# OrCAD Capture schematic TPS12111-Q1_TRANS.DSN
size B; title: TPS12111-Q1: 100-V Smart High Side Driver with Protection; rev: 1.0; note: Datasheet: SLUSEQ9A; note: and Diagnostics
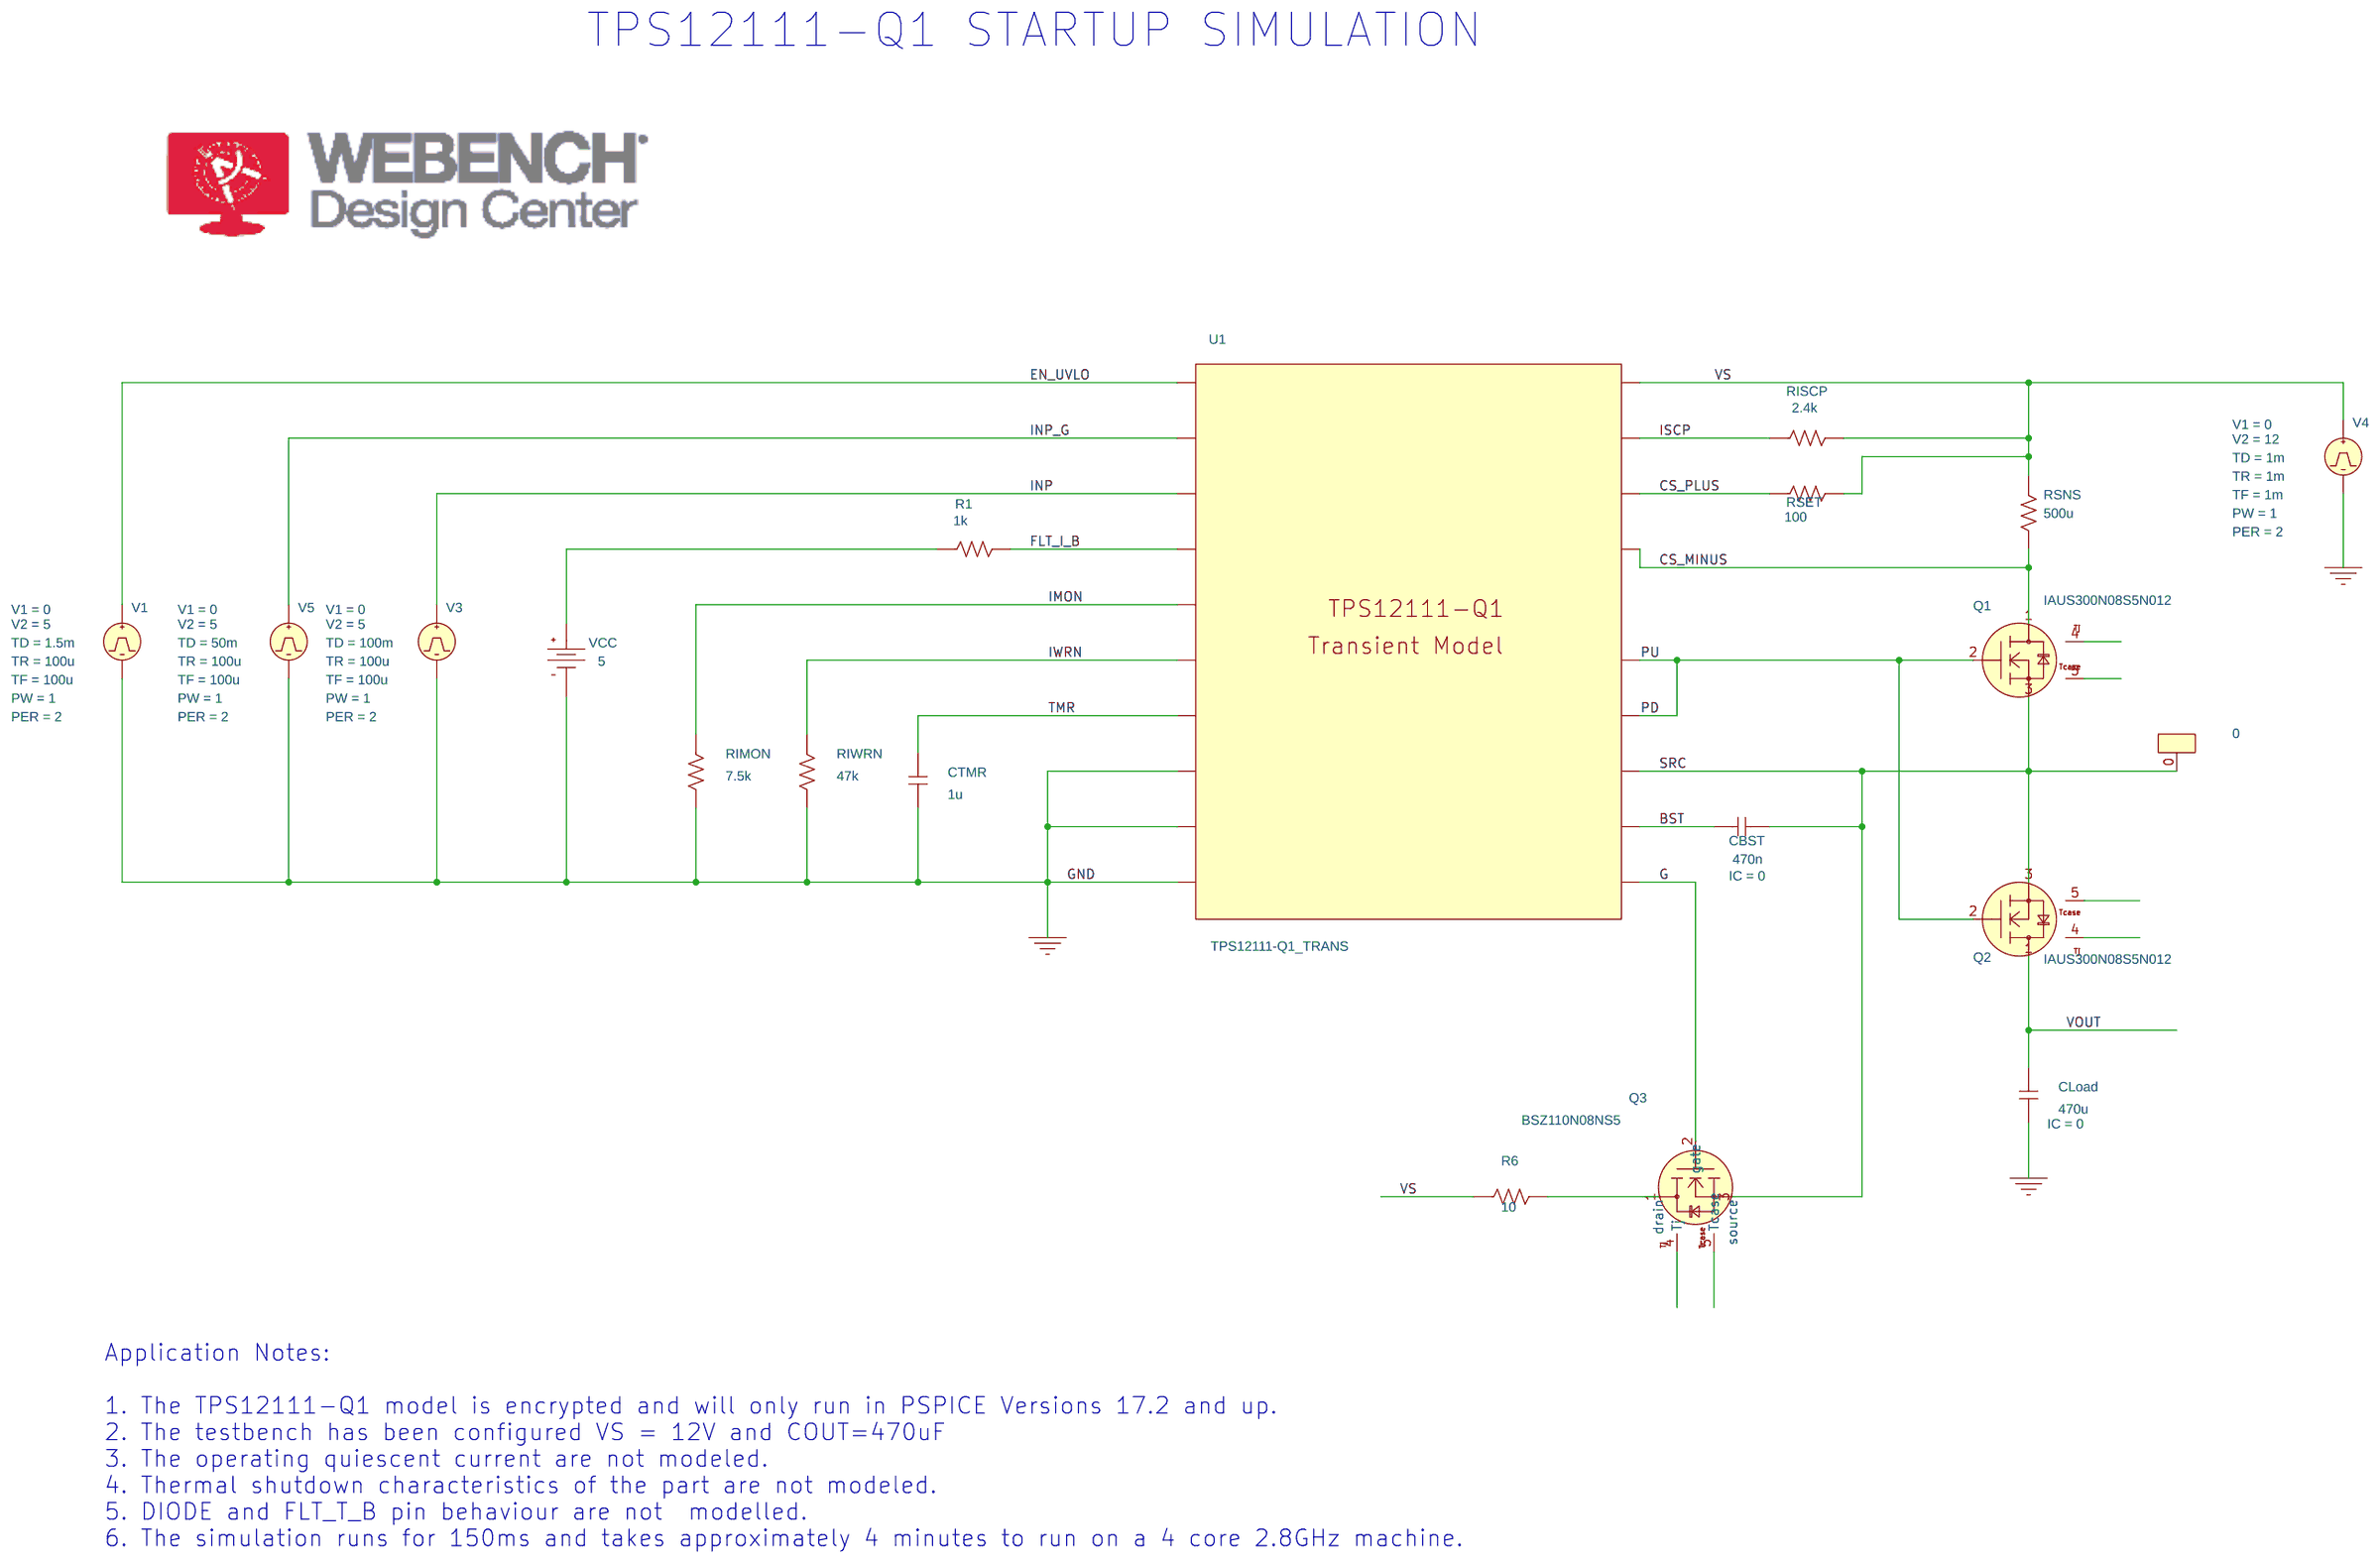
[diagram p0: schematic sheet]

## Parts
CBST  470n  [RAD/CK05]
CLoad  470u  [RAD/CK05]
CTMR  1u  [RAD/CK05]
IC1  0
Q1  IAUS300N08S5N012
Q2  IAUS300N08S5N012
Q3  BSZ110N08NS5
R1  1k  [AX/RC05]
R6  10  [AX/RC05]
RIMON  7.5k  [AX/RC05]
RISCP  2.4k  [AX/RC05]
RIWRN  47k  [AX/RC05]
RSET  100  [AX/RC05]
RSNS  500u  [AX/RC05]
U1  TPS12111-Q1_TRANS
V1  VPULSE
V3  VPULSE
V4  VPULSE
V5  VPULSE
VCC  VDC

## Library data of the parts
CBST CLoad = C: IC: 0
CTMR = C
IC1 = IC1
Q1 Q2 = IAUS300N08S5N012
Q3 = BSZ110N08NS5
R1 R6 RIMON RISCP RIWRN RSET RSNS = R
U1 = TPS12111-Q1_TRANS: PSpiceTemplate: X^@REFDES  %BST %CS_MINUS %CS_PLUS %DIODE %EN_UVLO %FLT_I_B %FLT_T_B %G %GND %IMON %INP %INP_G %ISCP %IWRN %PD %PU %SRC %TMR %VS @MODEL
V1 = VPULSE: PER: 2; PW: 1; TD: 1.5m; TF: 100u; TR: 100u; V1: 0; V2: 5
V3 = VPULSE: PER: 2; PW: 1; TD: 100m; TF: 100u; TR: 100u; V1: 0; V2: 5
V4 = VPULSE: PER: 2; PW: 1; TD: 1m; TF: 1m; TR: 1m; V1: 0; V2: 12
V5 = VPULSE: PER: 2; PW: 1; TD: 50m; TF: 100u; TR: 100u; V1: 0; V2: 5
VCC = VDC: DC: 5

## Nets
0: CLoad.2 CTMR.2 RIMON.2 RIWRN.2 U1.DIODE U1.FLT_T_B U1.GND V1.2(-) V3.2(-) V4.2(-) V5.2(-) VCC.1(-)
BST: CBST.1 U1.BST
CS_MINUS: Q1.1(drain) RSNS.2 U1.CS_MINUS
CS_PLUS: RSET.1 U1.CS_PLUS
EN_UVLO: U1.EN_UVLO V1.1(+)
FLT_I_B: R1.2 U1.FLT_I_B
G: Q3.2(gate) U1.G
IMON: RIMON.1 U1.IMON
INP: U1.INP V3.1(+)
INP_G: U1.INP_G V5.1(+)
ISCP: RISCP.1 U1.ISCP
IWRN: RIWRN.1 U1.IWRN
PD: Q1.2(gate) Q2.2(gate) U1.PD U1.PU
SRC: CBST.2 IC1.0(+) Q1.3(source) Q2.3(source) Q3.3(source) U1.SRC
TMR: CTMR.1 U1.TMR
VOUT: CLoad.1 Q2.1(drain)
VS: R6.1 RISCP.2 RSET.2 RSNS.1 U1.VS V4.1(+)
N16579999: R1.1 VCC.0(+)
N16580517: Q3.1(drain) R6.2

Not connected (* = marked no-connect by the designer): Q1 4(Tj) 5(Tcase); Q2 4(Tj) 5(Tcase); Q3 4(Tj) 5(Tcase)

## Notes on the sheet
- TPS12111-Q1 STARTUP SIMULATION
- Application Notes:
  1. The TPS12111-Q1 model is encrypted and will only run in PSPICE Versions 17.2 and up.
  2. The testbench has been configured VS = 12V and COUT=470uF
  3. The operating quiescent current are not modeled.
  4. Thermal shutdown characteristics of the part are not modeled.
  5. DIODE and FLT_T_B pin behaviour are not  modelled.
  6. The simulation runs for 150ms and takes approximately 4 minutes to run on a 4 core 2.8GHz machine.
